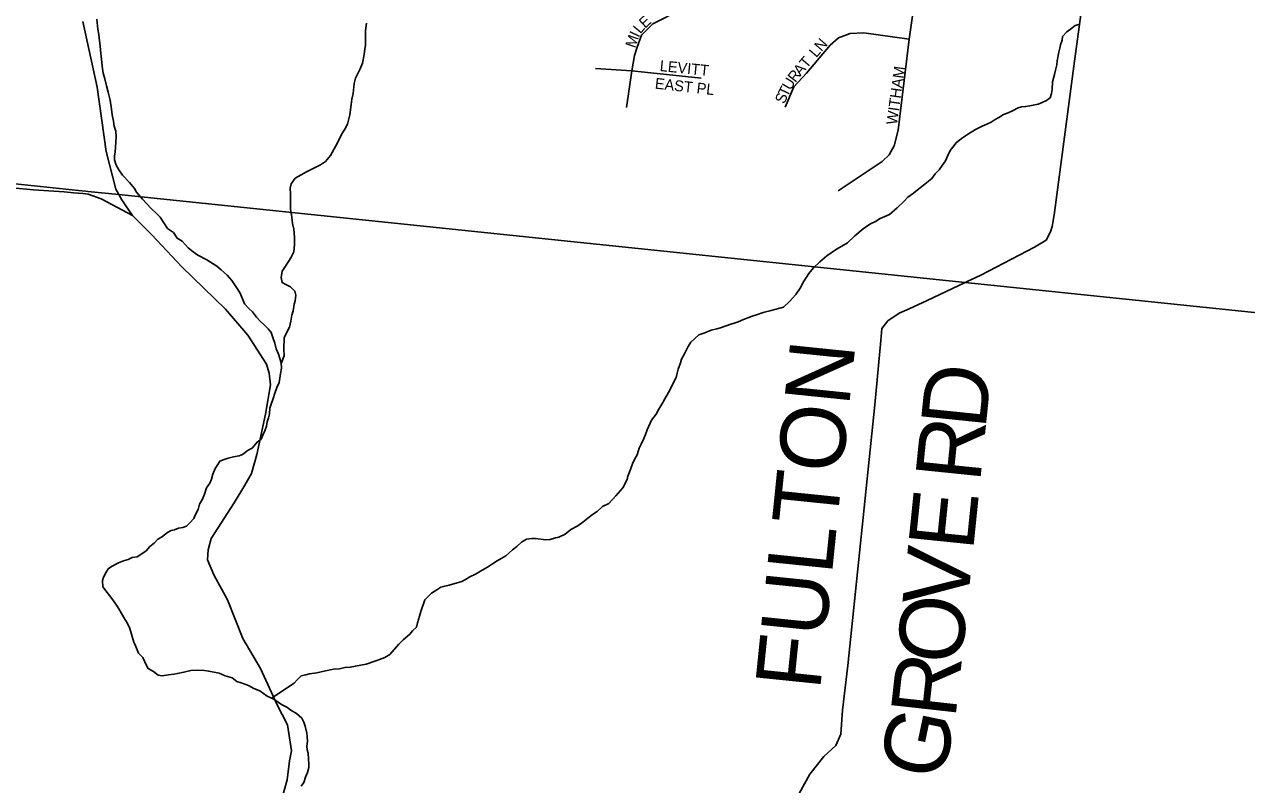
# Model space of a CAD drawing. Extents: x 1310247 to 1664935, y 235267 to 584339.
# Drawn here: x 1457266 to 1462894, y 387159 to 390661 of the extents above; entities that cross this region are included whole.
import ezdxf

# ---------------------------------------------------------------- set-up
doc = ezdxf.new("R2010")
doc.units = 0
for name, color, linetype in [('GM_X_County_Road', 7, 'Continuous'), ('GM_X_County_Road_Text', 7, 'Continuous'), ('GM_X_Minor_River', 7, 'Continuous'), ('GM_X_Township', 7, 'Continuous'), ('GM_X_Township_Road', 7, 'Continuous'), ('GM_X_Township_Subdivision', 7, 'Continuous'), ('GM_X_Township_Subdivision_Text', 7, 'Continuous')]:
    doc.layers.add(name, color=color, linetype=linetype)

msp = doc.modelspace()

# ---------------------------------------------------------------- linework, layer by layer
at = {"layer": 'GM_X_County_Road'}
for points in [[(1462404.7, 392817.9), (1462358.7, 392433.7), (1462254, 391613.4), (1462098.9, 390469.2), (1462010.3, 389793.7), (1462003.2, 389755.8), (1461998.5, 389729.9), (1461991.9, 389706), (1461970.8, 389666.4), (1461917.1, 389634.8), (1461669.9, 389506), (1461608.4, 389476.8)], [(1457733.3, 389825.3), (1457714.7, 389852.1), (1457700.9, 389876.7), (1457686.7, 389901.8), (1457642.2, 390075.2), (1457601.5, 390372.3), (1457535.7, 390674.5)], [(1458448.9, 387082.6), (1458475.9, 387180.8), (1458487.4, 387268), (1458496.3, 387314), (1458477.1, 387433.6), (1458429.3, 387529.3), (1458353.2, 387693.7), (1458272.7, 387832), (1458202.2, 388010.3), (1458138.6, 388125.6), (1458110, 388194.4), (1458113, 388240.4), (1458126.1, 388292.3), (1458231.6, 388456.6), (1458281.3, 388537.9), (1458312.5, 388591.4), (1458336.4, 388679.1), (1458376.2, 388864.9), (1458399.8, 388999.9), (1458393.6, 389054.7), (1458381.8, 389095.1), (1458294.7, 389228.7), (1458192.1, 389348.7), (1457991.8, 389544.6), (1457852.6, 389691.8), (1457764.1, 389780.9), (1457733.3, 389825.3)], [(1461608.4, 389476.8), (1461599, 389472.4), (1461422.8, 389388.6), (1461340.3, 389350.4), (1461295.2, 389330.6), (1461241.8, 389294.7), (1461215.3, 389259.5), (1461210.4, 389204.6), (1461182.9, 388909), (1461058.5, 387707.7), (1461034, 387501.5), (1461025.6, 387391.4), (1461002.7, 387338.8), (1460947.7, 387287.6), (1460882.5, 387206.4), (1460834.1, 387117.4), (1460813.3, 387063.1), (1460781.5, 387026.6), (1460748.7, 386997.3), (1460689.6, 386963.8), (1460580.4, 386915.6), (1460414.3, 386843.8)]]:
    msp.add_lwpolyline(points, dxfattribs=at)
at = {"layer": 'GM_X_Minor_River'}
for points in [[(1458072.1, 388450.2), (1458086.6, 388474), (1458095, 388496), (1458105.5, 388525.9), (1458119.9, 388547.7), (1458128.3, 388565.7), (1458134.7, 388589.6), (1458145.2, 388615.5), (1458157.5, 388633.4), (1458165.8, 388649.3), (1458186, 388657), (1458204.2, 388662.7), (1458228.4, 388668.3), (1458254.6, 388673.9), (1458270.7, 388679.6), (1458297.1, 388699.2), (1458315.4, 388708.9), (1458337.9, 388736.6), (1458356.2, 388750.4), (1458364.5, 388768.3), (1458372.9, 388788.2), (1458381.3, 388810.1), (1458383.6, 388830.2), (1458390, 388848.1), (1458394.3, 388866.1), (1458396.7, 388892.2), (1458403.1, 388912.1), (1458411.5, 388938.1), (1458420, 388962), (1458428.4, 388988), (1458438.9, 389011.9), (1458443.2, 389031.9), (1458445.6, 389051.9), (1458450, 389077.9), (1458448.4, 389102), (1458437.1, 389142.4), (1458425.4, 389166.7), (1458419.8, 389192.9), (1458410.2, 389219.1), (1458402.6, 389241.3), (1458388.8, 389257.7), (1458369.1, 389278.1), (1458353.3, 389292.4), (1458335.5, 389312.8), (1458315.9, 389337.2), (1458300.1, 389351.5), (1458280.4, 389374), (1458259.1, 389422.5), (1458243.5, 389448.9), (1458221.9, 389481.4), (1458200.3, 389505.8), (1458172.6, 389530.4), (1458152.8, 389546.8), (1458107.1, 389575.7), (1458065.3, 389598.5), (1458043.5, 389613), (1458019.7, 389631.4), (1457992.1, 389662), (1457970.3, 389676.5), (1457952.7, 389702.9), (1457924.9, 389721.4), (1457911.1, 389741.7), (1457891.6, 389772.2), (1457875.8, 389788.5), (1457848.1, 389815.1), (1457810.7, 389855.9), (1457783.1, 389888.5), (1457773.4, 389904.7), (1457749.8, 389933.2), (1457718.2, 389965.9), (1457700.5, 389990.3), (1457688.9, 390012.6), (1457681.2, 390036.8), (1457681.5, 390054.8), (1457683.9, 390072.9), (1457686.2, 390094.9), (1457686.6, 390119), (1457689, 390143), (1457687.5, 390169.2), (1457679.8, 390191.4), (1457676.2, 390215.5), (1457670.7, 390243.7), (1457667.1, 390269.9), (1457661.8, 390312.1), (1457652.3, 390348.4), (1457644.8, 390378.7), (1457637.3, 390410.9), (1457629.7, 390437.1), (1457624.3, 390469.3), (1457620.8, 390501.5), (1457617.4, 390541.7), (1457615.8, 390561.8), (1457610.4, 390598), (1457608.6, 390614.1), (1457605, 390638.3), (1457603.3, 390654.4), (1457599.8, 390684.5)], [(1458448.6, 389099.3), (1458463, 389133.9), (1458461.5, 389164), (1458462.4, 389218.2), (1458487.3, 389266), (1458493.8, 389294), (1458498.3, 389322), (1458504.6, 389341.9), (1458509.2, 389372), (1458513.4, 389388), (1458515.9, 389414), (1458512.2, 389432.1), (1458492.4, 389452.6), (1458470.5, 389463), (1458452.6, 389471.3), (1458449, 389495.5), (1458453.5, 389523.5), (1458467.9, 389547.3), (1458482.4, 389569.1), (1458492.7, 389585), (1458507.2, 389612.9), (1458509.8, 389647), (1458510.3, 389677.1), (1458508.7, 389701.2), (1458506.9, 389717.2), (1458501.3, 389743.5), (1458499.6, 389759.5), (1458496, 389783.7), (1458492.4, 389807.8), (1458490.9, 389836), (1458491.6, 389880.1), (1458490, 389906.2), (1458494.4, 389926.2), (1458512.9, 389952), (1458541.2, 389967.6), (1458565.6, 389981.2), (1458612.1, 390004.5), (1458630.3, 390014.2), (1458652.7, 390029.8), (1458675.2, 390057.5), (1458700.1, 390101.3), (1458731.2, 390160.9), (1458741.5, 390178.8), (1458753.9, 390200.7), (1458764.7, 390244.6), (1458771.5, 390292.7), (1458773.9, 390316.8), (1458780.4, 390342.7), (1458785.2, 390388.8), (1458791.6, 390412.8), (1458812.4, 390456.6), (1458822.9, 390482.5), (1458831.6, 390522.5), (1458834, 390548.5), (1458836.3, 390564.5), (1458836.7, 390590.6), (1458837, 390608.7), (1458837.4, 390630.8), (1458842, 390666.8)], [(1460618, 389317.1), (1460642.2, 389324.7), (1460668.4, 389334.2), (1460698.7, 389341.8), (1460745, 389353), (1460761.2, 389358.7), (1460789.7, 389384.3), (1460818.4, 389415.9), (1460838.9, 389445.7), (1460853.5, 389475.5), (1460878.2, 389513.2), (1460900.7, 389538.9), (1460929.3, 389566.5), (1460961.9, 389594.1), (1461006.6, 389625.4), (1461030.9, 389639), (1461057.2, 389654.6), (1461089.9, 389686.2), (1461128.6, 389719.6), (1461159.1, 389741.2), (1461185.3, 389752.7), (1461207.7, 389766.4), (1461227.9, 389776.1), (1461250.1, 389785.7), (1461284.7, 389815.2), (1461317.4, 389846.8), (1461333.8, 389864.5), (1461360.2, 389884.2), (1461384.6, 389903.8), (1461413.1, 389925.4), (1461429.3, 389939.1), (1461445.6, 389950.9), (1461460, 389972.7), (1461478.4, 389990.5), (1461492.8, 390010.3), (1461507.2, 390032.1), (1461517.6, 390054), (1461530.1, 390079.9), (1461542.4, 390095.7), (1461556.8, 390115.5), (1461581.2, 390135.2), (1461613.7, 390156.7), (1461646.1, 390176.2), (1461676.5, 390191.7), (1461698.7, 390201.4), (1461719, 390211.1), (1461737.2, 390222.8), (1461753.4, 390232.5), (1461775.8, 390246.2), (1461796, 390253.9), (1461816.2, 390263.5), (1461842.5, 390277.1), (1461858.6, 390280.9), (1461876.7, 390282.6), (1461896.9, 390286.2), (1461935.1, 390293.6), (1461953.3, 390301.3), (1461973.6, 390311), (1461989.8, 390322.7), (1461996.2, 390342.7), (1461998.5, 390360.7), (1462001.1, 390396.8), (1462009.7, 390430.8), (1462014, 390450.8), (1462020.5, 390474.7), (1462022.8, 390492.7), (1462029.5, 390532.8), (1462033.8, 390550.8), (1462038.1, 390566.7), (1462044.5, 390588.7), (1462046.7, 390604.7), (1462067.2, 390626.4), (1462089.5, 390644.1), (1462105.8, 390655.9), (1462126, 390661.5)], [(1458403.6, 387557.4), (1458507.9, 387625.6), (1458522.3, 387641.4), (1458540.6, 387659.1), (1458562.8, 387664.7), (1458578.9, 387668.5), (1458613.1, 387673.9), (1458653.4, 387683.2), (1458689.7, 387690.6), (1458717.8, 387692.1), (1458742, 387697.8), (1458766.1, 387699.3), (1458790.3, 387704.9), (1458840.6, 387714.1), (1458885.1, 387729.4), (1458901.2, 387735.1), (1458925.5, 387744.7), (1458949.8, 387758.4), (1458990.7, 387805.8), (1459011.1, 387825.5), (1459041.7, 387851.1), (1459054, 387867), (1459072.3, 387884.7), (1459076.7, 387904.7), (1459085.2, 387934.7), (1459091.6, 387956.6), (1459110.6, 388010.5), (1459141.2, 388040.1), (1459165.5, 388055.7), (1459183.8, 388067.5), (1459202, 388073.1), (1459222.1, 388076.8), (1459258.4, 388088.2), (1459280.6, 388093.9), (1459296.8, 388103.6), (1459317.1, 388115.3), (1459343.4, 388128.9), (1459373.8, 388146.4), (1459398.2, 388160.1), (1459422.5, 388175.7), (1459442.8, 388189.4), (1459483.3, 388212.8), (1459513.9, 388240.3), (1459534.3, 388256), (1459554.7, 388275.8), (1459579, 388289.4), (1459603.1, 388293), (1459619.2, 388292.7), (1459667.2, 388285.8), (1459687.3, 388287.5), (1459711.6, 388295.1), (1459727.7, 388298.8), (1459756, 388312.4), (1459782.5, 388334), (1459814.9, 388351.5), (1459837.2, 388367.2), (1459861.6, 388386.8), (1459882, 388402.5), (1459904.3, 388416.2), (1459928.8, 388439.9), (1459957.1, 388453.4), (1459989.8, 388489), (1460022.6, 388526.5), (1460041.3, 388564.4), (1460045.6, 388580.3), (1460058.2, 388614.3), (1460066.6, 388636.2), (1460079.1, 388662.1), (1460087.3, 388678), (1460097.9, 388707.9), (1460106.2, 388727.8), (1460118.7, 388753.7), (1460127.1, 388771.6), (1460133.4, 388793.6), (1460154.3, 388837.4), (1460174.8, 388865.1), (1460187.2, 388889), (1460205.8, 388918.8), (1460216.1, 388936.7), (1460232.7, 388964.5), (1460243, 388984.4), (1460251.4, 389002.3), (1460268, 389034.1), (1460272.3, 389054.1), (1460276.6, 389072.1), (1460287.2, 389102), (1460291.5, 389118), (1460305.9, 389143.9), (1460322.6, 389177.7), (1460334.9, 389197.5), (1460353.3, 389213.3), (1460371.6, 389231), (1460399.9, 389240.6), (1460428.2, 389252.1), (1460454.4, 389257.7), (1460472.5, 389263.4), (1460519, 389280.6), (1460535.1, 389284.4), (1460553.3, 389290.1), (1460577.6, 389301.7), (1460618, 389317.1)], [(1458540.1, 387151.2), (1458552.5, 387169), (1458560.9, 387193), (1458569.3, 387214.9), (1458575.7, 387236.9), (1458576, 387253), (1458574.3, 387275.1), (1458572.8, 387303.2), (1458569, 387319.3), (1458567.3, 387335.4), (1458569.7, 387359.5), (1458568, 387379.6), (1458566.3, 387395.7), (1458558.8, 387427.9), (1458553.1, 387446.1), (1458543.4, 387464.3), (1458519.7, 387486.8), (1458493.8, 387501.3), (1458474, 387515.7), (1458450.1, 387528.2), (1458434.2, 387538.5), (1458414.4, 387552.9), (1458384.5, 387565.5), (1458350.8, 387590.1), (1458322.8, 387600.7), (1458299, 387615.1), (1458265.1, 387627.8), (1458245.1, 387634.2), (1458223.3, 387650.6), (1458191.3, 387659.2), (1458163.4, 387671.7), (1458115.4, 387680.6), (1458095.4, 387685), (1458065.3, 387685.5), (1458033.2, 387684), (1458000.9, 387676.6), (1457970.7, 387671.1), (1457954.6, 387667.3), (1457930.5, 387663.8), (1457900.3, 387660.3), (1457882.3, 387662.6), (1457860.5, 387679), (1457836.6, 387693.5), (1457826.9, 387709.7), (1457811.4, 387744.1), (1457791.6, 387764.5), (1457780.1, 387794.9), (1457770.4, 387815.1), (1457762.8, 387841.3), (1457751.4, 387877.7), (1457739.8, 387904), (1457724.1, 387928.3), (1457712.5, 387950.6), (1457700.7, 387968.9), (1457691, 387985.1), (1457669.4, 388015.6), (1457647.8, 388044.1), (1457628.2, 388070.5), (1457626.6, 388098.7), (1457630.9, 388114.6), (1457641.3, 388134.5), (1457651.6, 388152.4), (1457667.9, 388164.2), (1457700.3, 388179.7), (1457722.5, 388189.3), (1457744.7, 388195), (1457762.9, 388204.7), (1457785, 388208.3), (1457807.3, 388222), (1457827.7, 388235.7), (1457844, 388255.5), (1457864.4, 388271.2), (1457880.7, 388289), (1457897, 388298.7), (1457925.4, 388320.3), (1457941.7, 388330), (1457957.7, 388331.8), (1457975.9, 388339.5), (1457996.1, 388343.1), (1458012.2, 388348.9), (1458028.5, 388364.7), (1458046.9, 388384.4), (1458053.2, 388400.4), (1458065.7, 388426.2), (1458072.1, 388450.2)]]:
    msp.add_lwpolyline(points, dxfattribs=at)
at = {"layer": 'GM_X_Township'}
for points in [[(1469108.8, 388730.1), (1468217, 388814.3), (1467476, 388884.4), (1466989.5, 388930.4), (1465130.1, 389106.1), (1463285.7, 389297.4), (1461599, 389472.4), (1457700.9, 389876.7), (1457558.4, 389891.5), (1457547.9, 389892.5), (1457515, 389896), (1457076.9, 389941.4), (1455486, 390106.4), (1453121.7, 390351.6), (1453275.9, 391587.6), (1453354.5, 392217.3), (1453506.1, 393433.1), (1453769.5, 395544.2), (1454072.9, 397836.5)], [(1451682.2, 379093.4), (1452162.4, 382944.4), (1452825.6, 387979.7), (1452941.9, 388909.9), (1453121.7, 390351.6), (1455486, 390106.4), (1457076.9, 389941.4), (1457515, 389896), (1457547.9, 389892.5), (1457558.4, 389891.5), (1457700.9, 389876.7), (1461599, 389472.4), (1463285.7, 389297.4), (1465130.1, 389106.1), (1466989.5, 388930.4), (1467476, 388884.4), (1468217, 388814.3), (1469108.8, 388730.1)]]:
    msp.add_lwpolyline(points, dxfattribs=at)
at = {"layer": 'GM_X_Township_Road'}
msp.add_lwpolyline([(1457075.7, 389920.6), (1457308.1, 389899.5), (1457450.1, 389890.3), (1457492.4, 389885.2), (1457534.6, 389881.2), (1457559.8, 389878.5), (1457620.4, 389856.8), (1457764.1, 389780.9)], dxfattribs=at)
at = {"layer": 'GM_X_Township_Subdivision'}
for points in [[(1461014.3, 389893.9), (1461216.1, 390029.8), (1461248.8, 390059.4), (1461271.1, 390102), (1461290.3, 390173.6), (1461341.4, 390592.8), (1461386.2, 390918), (1461414.6, 391126.5), (1461456.7, 391462.8), (1461491.6, 391731.5), (1461507.7, 391855.1)], [(1460038.7, 390278.4), (1460064.2, 390446.6), (1460075.1, 390518.4), (1460087.8, 390556.3), (1460107.6, 390610.7), (1460159.8, 390662.9), (1460290.2, 390730), (1460485.3, 390831.8), (1460568.5, 390876.5), (1460677.9, 390934.9), (1460767.3, 390976), (1460824.5, 390990.9), (1460880.4, 390990.9), (1460955, 390985.9), (1461048.1, 390973.5), (1461386.2, 390918)], [(1460769.1, 390279.4), (1460808.9, 390372.8), (1460867.1, 390436.8), (1460976.3, 390564.6), (1461014.6, 390598.9), (1461068.2, 390619.2), (1461132.6, 390622.6), (1461341.4, 390592.8)], [(1459895.9, 390457.5), (1460064.2, 390446.6)], [(1460064.2, 390446.6), (1460383.3, 390412.7)]]:
    msp.add_lwpolyline(points, dxfattribs=at)

# ---------------------------------------------------------------- texts
at = {"layer": 'GM_X_County_Road_Text'}
for s, rotation, p in [('FULTON', 84.1528, (1460929.9, 387589.1)), ('D', 84.1321, (1461692, 388791.9)), ('R', 84.1511, (1461666.9, 388546.8)), ('E', 84.1549, (1461634.7, 388231.7)), ('V', 84.1536, (1461607.8, 387969.1)), ('O', 84.0802, (1461580.5, 387706)), ('R', 83.6751, (1461553.1, 387458.8)), ('G', 78.1271, (1461493.8, 387169.2))]:
    msp.add_text(s, height=300, rotation=rotation, dxfattribs=at).set_placement(p)
at = {"layer": 'GM_X_Township_Subdivision_Text'}
for s, rotation, p in [('E', 42.5071, (1460124.3, 390640.4)), ('L', 50.0091, (1460102.9, 390614.7)), ('M', 71.2368, (1460079, 390549)), ('I', 65.0386, (1460095.5, 390597.7)), ('LN', 49.0834, (1460912.7, 390504.8)), ('LEVITT', 354.1768, (1460190.4, 390446.4)), ('A', 49.7655, (1460840.1, 390421.3)), ('T', 49.7655, (1460868.5, 390454.9)), ('WITHAM', 82.1439, (1461284.5, 390196.3)), ('EAST PL', 353.6634, (1460167.8, 390365.3)), ('U', 58.4623, (1460794.2, 390354)), ('R', 52.6645, (1460816.5, 390390.4)), ('T', 64.2602, (1460779.6, 390323.4)), ('S', 67.1591, (1460766.2, 390291.6))]:
    msp.add_text(s, height=50, rotation=rotation, dxfattribs=at).set_placement(p)

doc.saveas('drawing.dxf')
